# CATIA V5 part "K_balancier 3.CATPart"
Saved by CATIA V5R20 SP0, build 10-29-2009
Part number: balancier 3
Publications: "demi largeur balancier", "epaisseur pieces", "largeur pneu", "decalage pneu", "Plan.00", "liaison 3/10", "liaison 3/5", "liaison 3/18 sur 3"
Bounding box of the stored display mesh (mm): x -30 to 300, y -770 to 50, z -50 to 50
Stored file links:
  G:\Khaled_CFAO_2011\SIL\SIL_GR2\mdardier\Khaled\CAD_ThinkMOTION\K_balancier 3.CATPart
  G:\Khaled_CFAO_2011\SIL\SIL_GR2\mdardier\Khaled\CAD_ThinkMOTION\K_ass_tandem.CATProduct
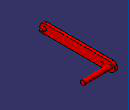
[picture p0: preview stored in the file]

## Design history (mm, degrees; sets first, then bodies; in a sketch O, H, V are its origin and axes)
External parameters (linked from other documents)
  `External.demi largeur balancier` = 50 mm
  `External.epaisseur pieces` = 30 mm
  `External.largeur pneu` = 200 mm
  `External.decalage pneu` = 100 mm
Set1
  Plane1 "Plan.00": linked copy from another document
  Point1 "liaison 3/10": linked copy from another document
  Point2 "liaison 3/5": linked copy from another document
  Point3 "liaison 3/18 sur 3": linked copy from another document
Set2
  Boundary1: Boundary face of Pad1 from Sketch1.A3
  Extract1: ExtractElem edge of Boundary1
  Boundary2: Boundary face of Pad1 from Sketch1.A3
Body1 (main body)
  Sketch1 on Plane1, origin (0, 0, 0), H (0, 1, 0), V (0, 0, 1)
    construction line L1 (-720, 0) -> (0, 0)
    point P1 (-720, 0)
    point P2 (0, 0)
    line L2 (-720, 50) -> (0, 50)
    line L3 (0, -50) -> (-720, -50)
    arc A1 centre (0, 0) radius 50 from (0, 50) to (0, -50) cw
    arc A2 centre (-720, 0) radius 50 from (-720, -50) to (-720, 50) cw
    reference projected point E1 (-720, 0) from Point1
    reference projected point E2 (0, 0) from Point2
    circle A3 centre (-720, 0) radius 20
    point P7 (-720, 0)
    reference projected point E3 (-720, 0) from Point1
    circle A4 centre (-85, 0) radius 12.5
    point P8 (-85, 0)
    reference projected point E4 (-85, 0) from Point3
    distance L1 L2 = 50 {= `External.demi largeur balancier`}
    radius A3 = 20 {= `External.demi largeur balancier` *2/5}
    radius A4 = 12.5 {= `External.demi largeur balancier` /4}
    tangency: A1 L2, A2 L2, A1 L3, A2 L3
    coincidence: P1 E1, P2 E2, P7 E3, P8 E4
  Pad1: profile Sketch1, direction (-1, 0, 0), length 30 {= `External.epaisseur pieces`}
  Sketch2 on start face of Pad1, origin (0, 0, 0), H (0, 1, 0), V (0, 0, 1)
    circle A1 centre (0, 0) radius 25
    point P1 (0, 0)
    reference projected point E1 (0, 0) from Point2
    radius A1 = 25 {= `External.demi largeur balancier` /2}
    coincidence: P1 E1
  Pad2: profile Sketch2, direction (1, 0, 0), length 300 {= `External.largeur pneu` +`External.decalage pneu`}
  Pad3: profile Extract1, length 45
  Fillet1: radius 10, on end face of Pad3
